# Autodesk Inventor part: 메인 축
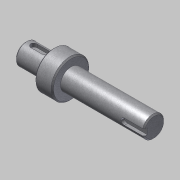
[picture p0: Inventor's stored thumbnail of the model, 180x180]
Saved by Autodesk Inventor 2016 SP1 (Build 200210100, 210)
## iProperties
Created: 2016-04
Part Number: 메인 축
Document SubType Name: Modeling
Designer: mdu
Density: 7.86 g/cm^3
Mass: 230.24 g
Surface Area: 74.3518 cm^2
Volume: 29.2926 cm^3
Material: 강철, 연강
Appearance: 금속-강(스테인리스, 브러시됨)
Author: mdu
Revision Number: 1
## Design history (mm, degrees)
sketch "스케치1"
  geometry: L1 (10.497, -57.5)-(112.497, -57.5); L2 (10.497, -66)-(32.497, -66); L3 (32.497, -72.5)-(46.5, -72.5); L4 (46.5, -66)-(112.497, -66); L5 (112.497, -66)-(112.497, -57.5); L6 (10.497, -66)-(10.497, -57.5); L7 (46.5, -69.749)-(46.5, -45.251) reference; L8 (46.5, -72.5)-(46.5, -66); L9 (32.497, -72.5)-(32.497, -66); L10 (32.497, -35)-(32.497, -80) reference; 3 further points
  constraints: 16 end point, 3 point on line, 2 parallel, 2 perpendicular, 1 collinear, 1 horizontal, 1 midpoint
  dimensions: "d0" = 17 diameter of L4 L1; "d1" = 30 diameter of L3 L1; "d2" = 22 distance of L2.start L2.end; "d3" = 65.99692 distance of L4.start L4.end (derived); "d5" = 17 diameter of L2 L1; "d19" = 80 distance between parallel lines of L5 L9
revolve "회전1" sketch "스케치1" stored, may be unused: angle "d4" = 90 deg
chamfer "모따기1" distance "d6" = 1; stored, may be unused: second distance "d7" = 2, angle "d8" = 45 deg
node "작업 평면1"
sketch "스케치2"
  geometry: L1 (-11, -7.5)-(-11, 7.5) reference; L2 (-4.5, 2.5)-(4.5, 2.5); L3 (4.5, -2.5)-(-4.5, -2.5); A1 r 2.5 centre (4.5, 0) between (4.5, -2.5) and (4.5, 2.5); A2 r 2.5 centre (-4.5, 0) between (-4.5, 2.5) and (-4.5, -2.5); 2 further points
  constraints: 4 end point, 4 point on circle, 4 tangent, 2 centre point, 1 horizontal alignment, 1 midpoint, 1 parallel, 1 perpendicular
  dimensions: "d9" = 5 distance between parallel lines of L3 L2; "d10" = 14 dimension on A1 A2; "d11" = 4 distance edge to line of A2 L1
extrude "돌출1" cut sketch "스케치2" distance "d12" = 3; taper "d13" = 0 deg
node "작업 평면2"
sketch "스케치3"
  geometry: L1 (32.998, 7.5)-(32.998, -7.5) reference; L2 (32.998, 2.5)-(17.498, 2.5); L3 (17.498, -2.5)-(32.998, -2.5); A1 r 2.5 centre (17.498, 0) between (17.498, 2.5) and (17.498, -2.5); 2 further points
  constraints: 4 end point, 2 perpendicular, 2 point on circle, 2 point on line, 2 tangent, 1 centre point, 1 horizontal alignment, 1 midpoint
  dimensions: "d14" = 5 distance between parallel lines of L3 L2; "d15" = 18 dimension on A1 L1
extrude "돌출2" cut sketch "스케치3" distance "d16" = 3; taper "d17" = 0 deg
node "솔리드1"
node "참조4"
node "참조5"
